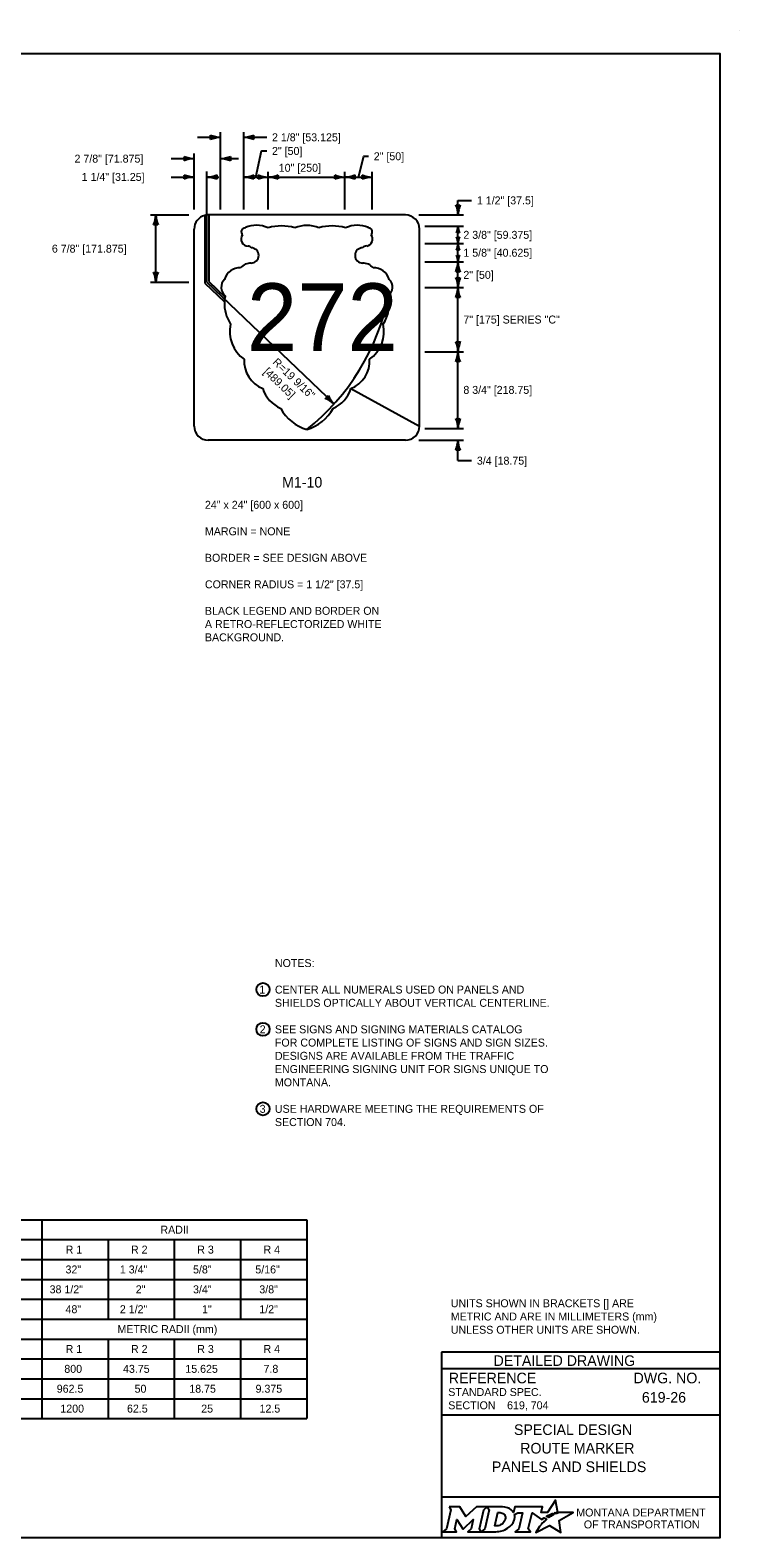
# Model space of a CAD drawing. Extents: x 49991.4 to 50021, y 49987.6 to 50011.4.
# Drawn here: x 50011.55 to 50016.9, y 49987.8 to 49999.18 of the extents above; entities that cross this region are included whole.
import ezdxf

# ---------------------------------------------------------------- set-up
doc = ezdxf.new("R2010")
doc.units = 0
for name, color, linetype in [('Default', 7, 'Continuous'), ('Level 1', 7, 'Continuous'), ('Level 2', 7, 'Continuous'), ('Level 3', 7, 'Continuous'), ('Level 4', 7, 'Continuous'), ('Level 5', 7, 'Continuous')]:
    doc.layers.add(name, color=color, linetype=linetype)

msp = doc.modelspace()

# ---------------------------------------------------------------- linework, layer by layer
at = {"layer": 'Default'}
for points in [[(50015.513, 49987.981), (50015.502, 49987.987), (50015.514, 49987.99), (50015.526, 49987.991), (50015.508, 49988.082), (50015.449, 49987.99), (50015.401, 49987.99), (50015.412, 49988.034), (50015.202, 49988.034), (50015.192, 49987.991), (50015.186, 49988)], [(50014.706, 49988.034), (50014.72, 49988.01), (50014.686, 49987.867), (50014.66, 49987.845), (50014.762, 49987.845), (50014.749, 49987.867), (50014.765, 49987.937), (50014.809, 49987.868), (50014.814, 49987.868), (50014.889, 49987.938), (50014.872, 49987.867), (50014.848, 49987.845), (50014.949, 49987.845), (50014.936, 49987.868), (50014.969, 49988.011)], [(50014.969, 49988.011), (50014.994, 49988.034), (50014.912, 49988.034), (50014.832, 49987.961), (50014.788, 49988.034), (50014.706, 49988.034)], [(50015.108, 49988.034), (50014.994, 49988.034), (50015.009, 49988.011), (50014.975, 49987.867), (50014.949, 49987.845), (50015.06, 49987.845)], [(50015.132, 49987.947), (50015.13, 49987.939), (50015.127, 49987.93), (50015.123, 49987.922), (50015.118, 49987.914), (50015.111, 49987.907), (50015.103, 49987.901), (50015.095, 49987.896), (50015.086, 49987.892), (50015.077, 49987.89), (50015.067, 49987.889), (50015.052, 49987.889), (50015.075, 49987.989), (50015.091, 49987.989), (50015.099, 49987.988), (50015.106, 49987.986), (50015.113, 49987.983), (50015.119, 49987.979), (50015.124, 49987.974), (50015.128, 49987.968), (50015.13, 49987.962), (50015.132, 49987.955), (50015.132, 49987.952), (50015.132, 49987.947)], [(50015.199, 49987.975), (50015.224, 49987.988), (50015.261, 49987.988), (50015.232, 49987.867), (50015.205, 49987.845), (50015.321, 49987.845), (50015.304, 49987.867), (50015.332, 49987.988), (50015.403, 49987.936), (50015.424, 49987.951), (50015.444, 49987.94)], [(50015.388, 49987.884), (50015.373, 49987.86), (50015.368, 49987.852), (50015.362, 49987.844), (50015.36, 49987.839), (50015.465, 49987.893), (50015.549, 49987.838), (50015.536, 49987.93), (50015.643, 49987.989), (50015.594, 49987.989), (50015.564, 49987.99), (50015.543, 49987.99), (50015.536, 49987.989), (50015.531, 49987.987), (50015.523, 49987.985), (50015.513, 49987.981)], [(50015.462, 49987.954), (50015.46, 49987.952), (50015.442, 49987.961), (50015.452, 49987.967), (50015.456, 49987.969), (50015.465, 49987.973), (50015.47, 49987.976), (50015.478, 49987.979), (50015.485, 49987.982), (50015.497, 49987.974), (50015.493, 49987.972), (50015.489, 49987.97), (50015.484, 49987.967), (50015.479, 49987.965), (50015.478, 49987.963), (50015.475, 49987.962), (50015.472, 49987.96), (50015.47, 49987.959), (50015.467, 49987.957), (50015.465, 49987.955), (50015.462, 49987.954)], [(50015.106, 49987.852), (50015.114, 49987.855), (50015.127, 49987.86), (50015.148, 49987.871)], [(50015.402, 49987.9), (50015.402, 49987.9)]]:
    msp.add_lwpolyline(points, dxfattribs=at)
for centre, radius, start, end in [((50015.087, 49987.973), 0.118, 300.9103, 339.1383), ((50015.131, 49987.955), 0.0709, 339.5329, 15.8582)]:
    msp.add_arc(centre, radius, start, end, dxfattribs=at)
for centre, major_axis, ratio, start_param, end_param in [((50015.106, 49987.986), (0.0834, -0.0037), 0.568097, 0.61298, 1.570796), ((50015.161, 49987.994), (0.0361, -0.0295), 0.469099, 1.225588, 1.570796), ((50015.433, 49987.93), (-0.0112, -0.0097), 0.021651, 3.157348, 6.283185), ((50015.06, 49987.993), (0, 0.148), 0.987302, 3.139398, 3.456847), ((50015.395, 49987.892), (-0.00694, -0.00806), 0.008222, 0, 3.137361), ((50015.412, 49987.911), (-0.0098, -0.0102), 0.016458, 3.141593, 6.279097)]:
    msp.add_ellipse(centre, major_axis=major_axis, ratio=ratio, start_param=start_param, end_param=end_param, dxfattribs=at)
at = {"layer": 'Level 1'}
for p, q in [((50016.9, 49999.176), (50016.9, 49999.176)), ((50012.863, 49997.779), (50012.863, 49997.267)), ((50012.894, 49997.782), (50012.889, 49997.782)), ((50014.377, 49997.782), (50012.894, 49997.782)), ((50012.894, 49997.782), (50012.894, 49997.28)), ((50012.783, 49996.188), (50012.783, 49997.675)), ((50014.483, 49996.188), (50014.483, 49997.675)), ((50012.863, 49997.267), (50013.011, 49997.125)), ((50012.894, 49997.28), (50013.015, 49997.163)), ((50013.966, 49996.471), (50014.483, 49996.188)), ((50013.966, 49996.471), (50014.483, 49996.188)), ((50014.377, 49996.082), (50012.889, 49996.082))]:
    msp.add_line(p, q, dxfattribs=at)
msp.add_lwpolyline([(49999.384, 49998.999), (50016.75, 49998.999), (50016.75, 49987.799), (49999.384, 49987.799)], close=True, dxfattribs=at)
for centre, radius, start, end in [((50012.889, 49997.675), 0.106, 103.9917, 180), ((50012.889, 49997.675), 0.106, 90, 103.9917), ((50014.377, 49997.675), 0.106, 0, 90), ((50013.19, 49997.599), 0.0531, 143.1471, 269.0651), ((50013.169, 49997.653), 0.031, 90.0026, 225.5829), ((50013.254, 49997.49), 0.213, 66.1312, 113.5565), ((50013.442, 49997.308), 0.39, 75.186, 105.0796), ((50013.633, 49997.463), 0.239, 90, 112.4922), ((50013.633, 49997.463), 0.239, 67.5078, 90), ((50013.824, 49997.308), 0.39, 74.9204, 104.814), ((50014.012, 49997.49), 0.213, 66.4435, 113.8688), ((50014.076, 49997.599), 0.0531, 280.3847, 36.852), ((50014.096, 49997.653), 0.031, 314.4154, 89.9974), ((50013.181, 49997.503), 0.0443, 44.427, 78.6548), ((50013.212, 49997.476), 0.0576, 270, 89.9981), ((50014.054, 49997.476), 0.0576, 90, 270), ((50014.085, 49997.503), 0.0443, 90, 135.5713), ((50013.133, 49997.255), 0.128, 90, 161.9199), ((50013.212, 49997.312), 0.106, 90, 138.1904), ((50014.054, 49997.312), 0.106, 41.8103, 90), ((50014.133, 49997.255), 0.128, 18.0801, 90.0009), ((50013.071, 49997.235), 0.0841, 135.1875, 230.255), ((50014.195, 49997.235), 0.0841, 309.745, 44.8125), ((50013.294, 49997.113), 0.283, 169.8942, 177.5491), ((50013.294, 49997.113), 0.283, 168.2757, 169.8942), ((50013.972, 49997.113), 0.283, 326.8525, 11.7243), ((50013.294, 49997.113), 0.283, 177.5491, 213.1475), ((50013.308, 49996.902), 0.257, 167.4175, 234.7502), ((50013.958, 49996.902), 0.257, 305.2498, 12.5825), ((50013.385, 49996.68), 0.226, 176.9135, 247.903), ((50013.881, 49996.68), 0.226, 292.097, 3.0865), ((50013.536, 49996.548), 0.248, 197.9076, 246.1525), ((50013.73, 49996.548), 0.248, 293.8475, 342.0924), ((50013.733, 49996.487), 0.341, 209.2235, 252.8916), ((50013.533, 49996.487), 0.341, 287.1084, 330.7765), ((50012.889, 49996.188), 0.106, 180, 270), ((50014.377, 49996.188), 0.106, 270, 0)]:
    msp.add_arc(centre, radius, start, end, dxfattribs=at)
at = {"layer": 'Level 2'}
for p, q in [((50005.005, 49990.199), (50013.633, 49990.199)), ((50011.633, 49990.199), (50011.633, 49989.449)), ((50013.633, 49990.199), (50013.633, 49989.449)), ((50006.133, 49990.049), (50013.633, 49990.049)), ((50012.133, 49990.049), (50012.133, 49989.449)), ((50012.633, 49990.049), (50012.633, 49989.449)), ((50013.133, 49990.049), (50013.133, 49989.449)), ((50005.005, 49989.899), (50013.633, 49989.899)), ((50005.005, 49989.749), (50013.633, 49989.749)), ((50005.005, 49989.599), (50013.633, 49989.599)), ((50005.005, 49989.449), (50013.633, 49989.449)), ((50005.005, 49989.449), (50013.633, 49989.449)), ((50011.633, 49989.449), (50011.633, 49988.699)), ((50013.633, 49989.449), (50013.633, 49988.699)), ((50006.133, 49989.299), (50013.633, 49989.299)), ((50012.133, 49989.299), (50012.133, 49988.699)), ((50012.633, 49989.299), (50012.633, 49988.699)), ((50013.133, 49989.299), (50013.133, 49988.699)), ((50005.005, 49989.149), (50013.633, 49989.149)), ((50005.005, 49988.999), (50013.633, 49988.999)), ((50005.005, 49988.849), (50013.633, 49988.849)), ((50005.005, 49988.699), (50013.633, 49988.699))]:
    msp.add_line(p, q, dxfattribs=at)
for centre in [(50013.302, 49991.936), (50013.302, 49991.636), (50013.302, 49991.036)]:
    msp.add_circle(centre, 0.0501, dxfattribs=at)
at = {"layer": 'Level 3'}
for p, q in [((50012.982, 49997.822), (50012.982, 49998.407)), ((50013.157, 49997.822), (50013.157, 49998.407)), ((50012.808, 49998.367), (50012.982, 49998.367)), ((50013.157, 49998.367), (50013.33, 49998.367)), ((50012.61, 49998.206), (50012.783, 49998.206)), ((50012.783, 49997.822), (50012.783, 49998.246)), ((50012.982, 49998.206), (50013.117, 49998.206)), ((50012.61, 49998.067), (50012.784, 49998.067)), ((50012.878, 49997.273), (50012.878, 49998.108)), ((50012.878, 49998.067), (50012.969, 49998.067)), ((50013.157, 49998.067), (50013.341, 49998.067)), ((50013.341, 49997.822), (50013.341, 49998.107)), ((50013.341, 49998.067), (50013.92, 49998.067)), ((50013.92, 49997.822), (50013.92, 49998.107)), ((50013.92, 49998.067), (50014.126, 49998.067)), ((50014.126, 49997.822), (50014.126, 49998.107)), ((50014.773, 49997.782), (50014.773, 49997.891)), ((50014.773, 49997.891), (50014.876, 49997.891)), ((50012.453, 49997.782), (50012.743, 49997.782)), ((50012.493, 49997.273), (50012.493, 49997.782)), ((50014.477, 49997.782), (50014.814, 49997.782)), ((50014.523, 49997.696), (50014.814, 49997.696)), ((50014.773, 49997.566), (50014.773, 49997.696)), ((50014.523, 49997.566), (50014.814, 49997.566)), ((50014.773, 49997.425), (50014.773, 49997.566)), ((50014.523, 49997.427), (50014.814, 49997.427)), ((50014.773, 49997.233), (50014.773, 49997.425)), ((50012.453, 49997.273), (50012.743, 49997.273)), ((50014.523, 49997.234), (50014.814, 49997.234)), ((50014.773, 49996.751), (50014.773, 49997.233)), ((50014.523, 49996.749), (50014.814, 49996.749)), ((50014.773, 49996.17), (50014.773, 49996.751)), ((50014.523, 49996.17), (50014.814, 49996.17)), ((50014.477, 49996.082), (50014.814, 49996.082)), ((50014.773, 49995.927), (50014.773, 49996.082)), ((50014.773, 49995.927), (50014.876, 49995.927))]:
    msp.add_line(p, q, dxfattribs=at)
for points in [[(50013.249, 49998.067), (50013.292, 49998.264), (50013.33, 49998.264)], [(50014.023, 49998.067), (50014.064, 49998.224), (50014.098, 49998.224)]]:
    msp.add_lwpolyline(points, dxfattribs=at)
for centre, radius, start, end in [((50012.991, 49998.589), 0.222, 247.456, 267.6395), ((50012.853, 49998.367), 0.0548, 342.1388, 17.8612), ((50012.993, 49998.134), 0.233, 92.8273, 112.0772), ((50013.145, 49998.6), 0.233, 272.8273, 292.0772), ((50013.148, 49998.145), 0.222, 67.456, 87.6395), ((50013.285, 49998.367), 0.0548, 162.1388, 197.8612), ((50012.792, 49998.428), 0.222, 247.456, 267.6395), ((50012.655, 49998.206), 0.0548, 342.1388, 17.8612), ((50012.794, 49997.974), 0.233, 92.8273, 112.0772), ((50012.97, 49998.439), 0.233, 272.8273, 292.0772), ((50012.973, 49997.984), 0.222, 67.456, 87.6395), ((50013.11, 49998.206), 0.0548, 162.1388, 197.8612), ((50012.792, 49998.29), 0.222, 247.456, 267.6395), ((50012.655, 49998.067), 0.0548, 342.1388, 17.8612), ((50012.794, 49997.835), 0.233, 92.8273, 112.0772), ((50012.869, 49997.845), 0.222, 67.456, 87.6395), ((50012.867, 49998.3), 0.233, 272.8273, 292.0772), ((50013.007, 49998.067), 0.0548, 162.1388, 197.8612), ((50013.145, 49998.3), 0.233, 272.8273, 292.0772), ((50013.148, 49997.845), 0.222, 67.456, 87.6395), ((50013.285, 49998.067), 0.0548, 162.1388, 197.8612), ((50013.35, 49998.289), 0.222, 247.456, 267.6395), ((50013.213, 49998.067), 0.0548, 342.1388, 17.8612), ((50013.352, 49997.834), 0.233, 92.8273, 112.0772), ((50013.329, 49998.3), 0.233, 272.8273, 292.0772), ((50013.332, 49997.845), 0.222, 67.456, 87.6395), ((50013.469, 49998.067), 0.0548, 162.1388, 197.8612), ((50013.929, 49998.289), 0.222, 247.456, 267.6395), ((50013.792, 49998.067), 0.0548, 342.1388, 17.8612), ((50013.931, 49997.834), 0.233, 92.8273, 112.0772), ((50013.908, 49998.3), 0.233, 272.8273, 292.0772), ((50013.911, 49997.845), 0.222, 67.456, 87.6395), ((50014.048, 49998.067), 0.0548, 162.1388, 197.8612), ((50014.135, 49998.289), 0.222, 247.456, 267.6395), ((50013.998, 49998.067), 0.0548, 342.1388, 17.8612), ((50014.138, 49997.834), 0.233, 92.8273, 112.0772), ((50014.773, 49997.91), 0.0548, 252.1388, 287.8612), ((50014.541, 49997.77), 0.233, 2.8273, 22.0772), ((50014.996, 49997.773), 0.222, 157.456, 177.6395), ((50012.271, 49997.791), 0.222, 337.456, 357.6395), ((50012.726, 49997.793), 0.233, 182.8273, 202.0772), ((50012.493, 49997.653), 0.0548, 72.1388, 107.8612), ((50014.625, 49997.702), 0.148, 337.456, 357.6395), ((50014.773, 49997.61), 0.0365, 72.1388, 107.8612), ((50014.773, 49997.651), 0.0365, 252.1388, 287.8612), ((50014.618, 49997.558), 0.155, 2.8273, 22.0772), ((50014.922, 49997.56), 0.148, 157.456, 177.6395), ((50014.929, 49997.704), 0.155, 182.8273, 202.0772), ((50014.625, 49997.572), 0.148, 337.456, 357.6395), ((50014.773, 49997.48), 0.0365, 72.1388, 107.8612), ((50014.929, 49997.573), 0.155, 182.8273, 202.0772), ((50014.551, 49997.436), 0.222, 337.456, 357.6395), ((50014.773, 49997.512), 0.0365, 252.1388, 287.8612), ((50014.618, 49997.419), 0.155, 2.8273, 22.0772), ((50014.922, 49997.42), 0.148, 157.456, 177.6395), ((50015.006, 49997.438), 0.233, 182.8273, 202.0772), ((50012.493, 49997.401), 0.0548, 252.1388, 287.8612), ((50012.26, 49997.262), 0.233, 2.8273, 22.0772), ((50012.715, 49997.264), 0.222, 157.456, 177.6395), ((50014.773, 49997.298), 0.0548, 72.1388, 107.8612), ((50014.773, 49997.362), 0.0548, 252.1388, 287.8612), ((50014.541, 49997.222), 0.233, 2.8273, 22.0772), ((50014.996, 49997.224), 0.222, 157.456, 177.6395), ((50014.551, 49997.243), 0.222, 337.456, 357.6395), ((50014.773, 49997.105), 0.0548, 72.1388, 107.8612), ((50015.006, 49997.245), 0.233, 182.8273, 202.0772), ((50014.773, 49996.877), 0.0548, 252.1388, 287.8612), ((50014.541, 49996.737), 0.233, 2.8273, 22.0772), ((50014.996, 49996.74), 0.222, 157.456, 177.6395), ((50014.551, 49996.758), 0.222, 337.456, 357.6395), ((50015.006, 49996.76), 0.233, 182.8273, 202.0772), ((50014.773, 49996.621), 0.0548, 72.1388, 107.8612), ((50013.745, 49996.443), 0.0548, 298.3976, 334.1199), ((50013.685, 49996.179), 0.233, 49.0861, 68.3359), ((50013.998, 49996.509), 0.222, 203.7148, 223.8983), ((50014.773, 49996.298), 0.0548, 252.1388, 287.8612), ((50014.541, 49996.158), 0.233, 2.8273, 22.0772), ((50014.996, 49996.161), 0.222, 157.456, 177.6395), ((50014.551, 49996.091), 0.222, 337.456, 357.6395), ((50014.773, 49995.953), 0.0548, 72.1388, 107.8612), ((50015.006, 49996.093), 0.233, 182.8273, 202.0772)]:
    msp.add_arc(centre, radius, start, end, dxfattribs=at)
at = {"layer": 'Level 4'}
msp.add_line((50012.878, 49997.273), (50013.838, 49996.355), dxfattribs=at)
msp.add_arc((50012.551, 49997.515), 1.733, 308.6541, 348.5575, dxfattribs=at)
at = {"layer": 'Level 5'}
for p, q in [((50016.75, 49989.199), (50014.65, 49989.199)), ((50014.65, 49989.199), (50014.65, 49987.799)), ((50016.75, 49989.074), (50014.65, 49989.074)), ((50016.386, 49988.859), (50016.386, 49988.859)), ((50016.75, 49988.724), (50014.65, 49988.724)), ((50015.144, 49988.799), (50015.144, 49988.799)), ((50015.7, 49988.475), (50015.7, 49988.475)), ((50016.75, 49988.106), (50014.65, 49988.106))]:
    msp.add_line(p, q, dxfattribs=at)

# ---------------------------------------------------------------- texts
at = {"layer": 'Default'}
for s, p in [('MONTANA DEPARTMENT', (50015.666, 49987.96)), ('OF TRANSPORTATION', (50015.723, 49987.87))]:
    msp.add_text(s, height=0.06, dxfattribs=at).set_placement(p)
at = {"layer": 'Level 1'}
msp.add_text('272', height=0.51, dxfattribs=at).set_placement((50013.181, 49996.755))
at = {"layer": 'Level 2'}
for s, height, p in [('2 1/8" [53.125]', 0.06, (50013.37, 49998.337)), ('2" [50]', 0.06, (50013.37, 49998.234)), ('2 7/8" [71.875]', 0.06, (50011.88, 49998.176)), ('10" [250]', 0.06, (50013.421, 49998.107)), ('2" [50]', 0.06, (50014.138, 49998.194)), ('1 1/4" [31.25]', 0.06, (50011.934, 49998.038)), ('1 1/2" [37.5]', 0.06, (50014.916, 49997.861)), ('2 3/8" [59.375]', 0.06, (50014.814, 49997.601)), ('6 7/8" [171.875]', 0.06, (50011.709, 49997.497)), ('1 5/8" [40.625]', 0.06, (50014.814, 49997.466)), ('2" [50]', 0.06, (50014.814, 49997.299)), ('7" [175] SERIES "C"', 0.06, (50014.814, 49996.962)), ('8 3/4" [218.75]', 0.06, (50014.814, 49996.431)), ('3/4 [18.75]', 0.06, (50014.916, 49995.897)), ('M1-10', 0.08, (50013.446, 49995.724)), ('24" x 24" [600 x 600]', 0.06, (50012.864, 49995.564)), ('MARGIN = NONE', 0.06, (50012.864, 49995.364)), ('BORDER = SEE DESIGN ABOVE', 0.06, (50012.864, 49995.164)), ('CORNER RADIUS = 1 1/2" [37.5]', 0.06, (50012.864, 49994.964)), ('BLACK LEGEND AND BORDER ON ', 0.06, (50012.864, 49994.764)), ('A RETRO-REFLECTORIZED WHITE ', 0.06, (50012.864, 49994.664)), ('BACKGROUND.', 0.06, (50012.864, 49994.564)), ('NOTES:', 0.06, (50013.392, 49992.106)), ('1', 0.06, (50013.274, 49991.906)), ('CENTER ALL NUMERALS USED ON PANELS AND', 0.06, (50013.392, 49991.906)), ('SHIELDS OPTICALLY ABOUT VERTICAL CENTERLINE.', 0.06, (50013.392, 49991.806)), ('2', 0.06, (50013.277, 49991.606)), ('SEE SIGNS AND SIGNING MATERIALS CATALOG', 0.06, (50013.392, 49991.606)), ('FOR COMPLETE LISTING OF SIGNS AND SIGN SIZES.', 0.06, (50013.392, 49991.506)), ('DESIGNS ARE AVAILABLE FROM THE TRAFFIC ', 0.06, (50013.392, 49991.406)), ('ENGINEERING SIGNING UNIT FOR SIGNS UNIQUE TO ', 0.06, (50013.392, 49991.306)), ('MONTANA.', 0.06, (50013.392, 49991.206)), ('3', 0.06, (50013.277, 49991.006)), ('USE HARDWARE MEETING THE REQUIREMENTS OF ', 0.06, (50013.392, 49991.006)), ('SECTION 704.', 0.06, (50013.392, 49990.906)), ('RADII', 0.06, (50012.528, 49990.094)), ('R 1', 0.06, (50011.813, 49989.944)), ('R 2', 0.06, (50012.306, 49989.944)), ('R 3', 0.06, (50012.806, 49989.944)), ('R 4', 0.06, (50013.306, 49989.944)), ('32"', 0.06, (50011.812, 49989.794)), ('1 3/4"', 0.06, (50012.222, 49989.794)), (' 5/8"', 0.06, (50012.752, 49989.794)), (' 5/16"', 0.06, (50013.222, 49989.794)), ('38 1/2"', 0.06, (50011.692, 49989.644)), ('2"', 0.06, (50012.342, 49989.644)), (' 3/4"', 0.06, (50012.752, 49989.644)), (' 3/8"', 0.06, (50013.252, 49989.644)), ('48"', 0.06, (50011.812, 49989.494)), ('2 1/2"', 0.06, (50012.222, 49989.494)), ('1"', 0.06, (50012.842, 49989.494)), (' 1/2"', 0.06, (50013.252, 49989.494)), ('UNITS SHOWN IN BRACKETS [] ARE ', 0.06, (50014.719, 49989.539)), ('METRIC RADII (mm)', 0.06, (50012.204, 49989.344)), ('METRIC AND ARE IN MILLIMETERS (mm) ', 0.06, (50014.719, 49989.439)), ('UNLESS OTHER UNITS ARE SHOWN.', 0.06, (50014.719, 49989.339)), ('R 1', 0.06, (50011.813, 49989.194)), ('R 2', 0.06, (50012.306, 49989.194)), ('R 3', 0.06, (50012.806, 49989.194)), ('R 4', 0.06, (50013.306, 49989.194)), ('800', 0.06, (50011.803, 49989.044)), ('43.75', 0.06, (50012.246, 49989.044)), ('15.625', 0.06, (50012.716, 49989.044)), ('7.8', 0.06, (50013.306, 49989.044)), ('962.5', 0.06, (50011.746, 49988.894)), ('50', 0.06, (50012.333, 49988.894)), ('18.75', 0.06, (50012.746, 49988.894)), ('9.375', 0.06, (50013.246, 49988.894)), ('619-26', 0.08, (50016.161, 49988.819)), ('1200', 0.06, (50011.773, 49988.744)), ('62.5', 0.06, (50012.276, 49988.744)), ('25', 0.06, (50012.836, 49988.744)), ('12.5', 0.06, (50013.276, 49988.744)), ('619, 704', 0.06, (50015.144, 49988.769)), ('SPECIAL DESIGN', 0.08, (50015.196, 49988.575)), ('ROUTE MARKER', 0.08, (50015.243, 49988.435)), ('PANELS AND SHIELDS', 0.08, (50015.029, 49988.295))]:
    msp.add_text(s, height=height, dxfattribs=at).set_placement(p)
for s, p in [('R=19 9/16"', (50013.37, 49996.664)), ('[489.05]', (50013.301, 49996.592))]:
    msp.add_text(s, height=0.06, rotation=316.2587, dxfattribs=at).set_placement(p)
at = {"layer": 'Level 5'}
for s, height, p in [('DETAILED DRAWING', 0.0799, (50015.042, 49989.096)), ('REFERENCE', 0.08, (50014.704, 49988.965)), ('DWG. NO.', 0.08, (50016.098, 49988.965)), ('STANDARD SPEC.', 0.06, (50014.7, 49988.869)), ('SECTION', 0.06, (50014.7, 49988.769))]:
    msp.add_text(s, height=height, dxfattribs=at).set_placement(p)

doc.saveas('drawing.dxf')
